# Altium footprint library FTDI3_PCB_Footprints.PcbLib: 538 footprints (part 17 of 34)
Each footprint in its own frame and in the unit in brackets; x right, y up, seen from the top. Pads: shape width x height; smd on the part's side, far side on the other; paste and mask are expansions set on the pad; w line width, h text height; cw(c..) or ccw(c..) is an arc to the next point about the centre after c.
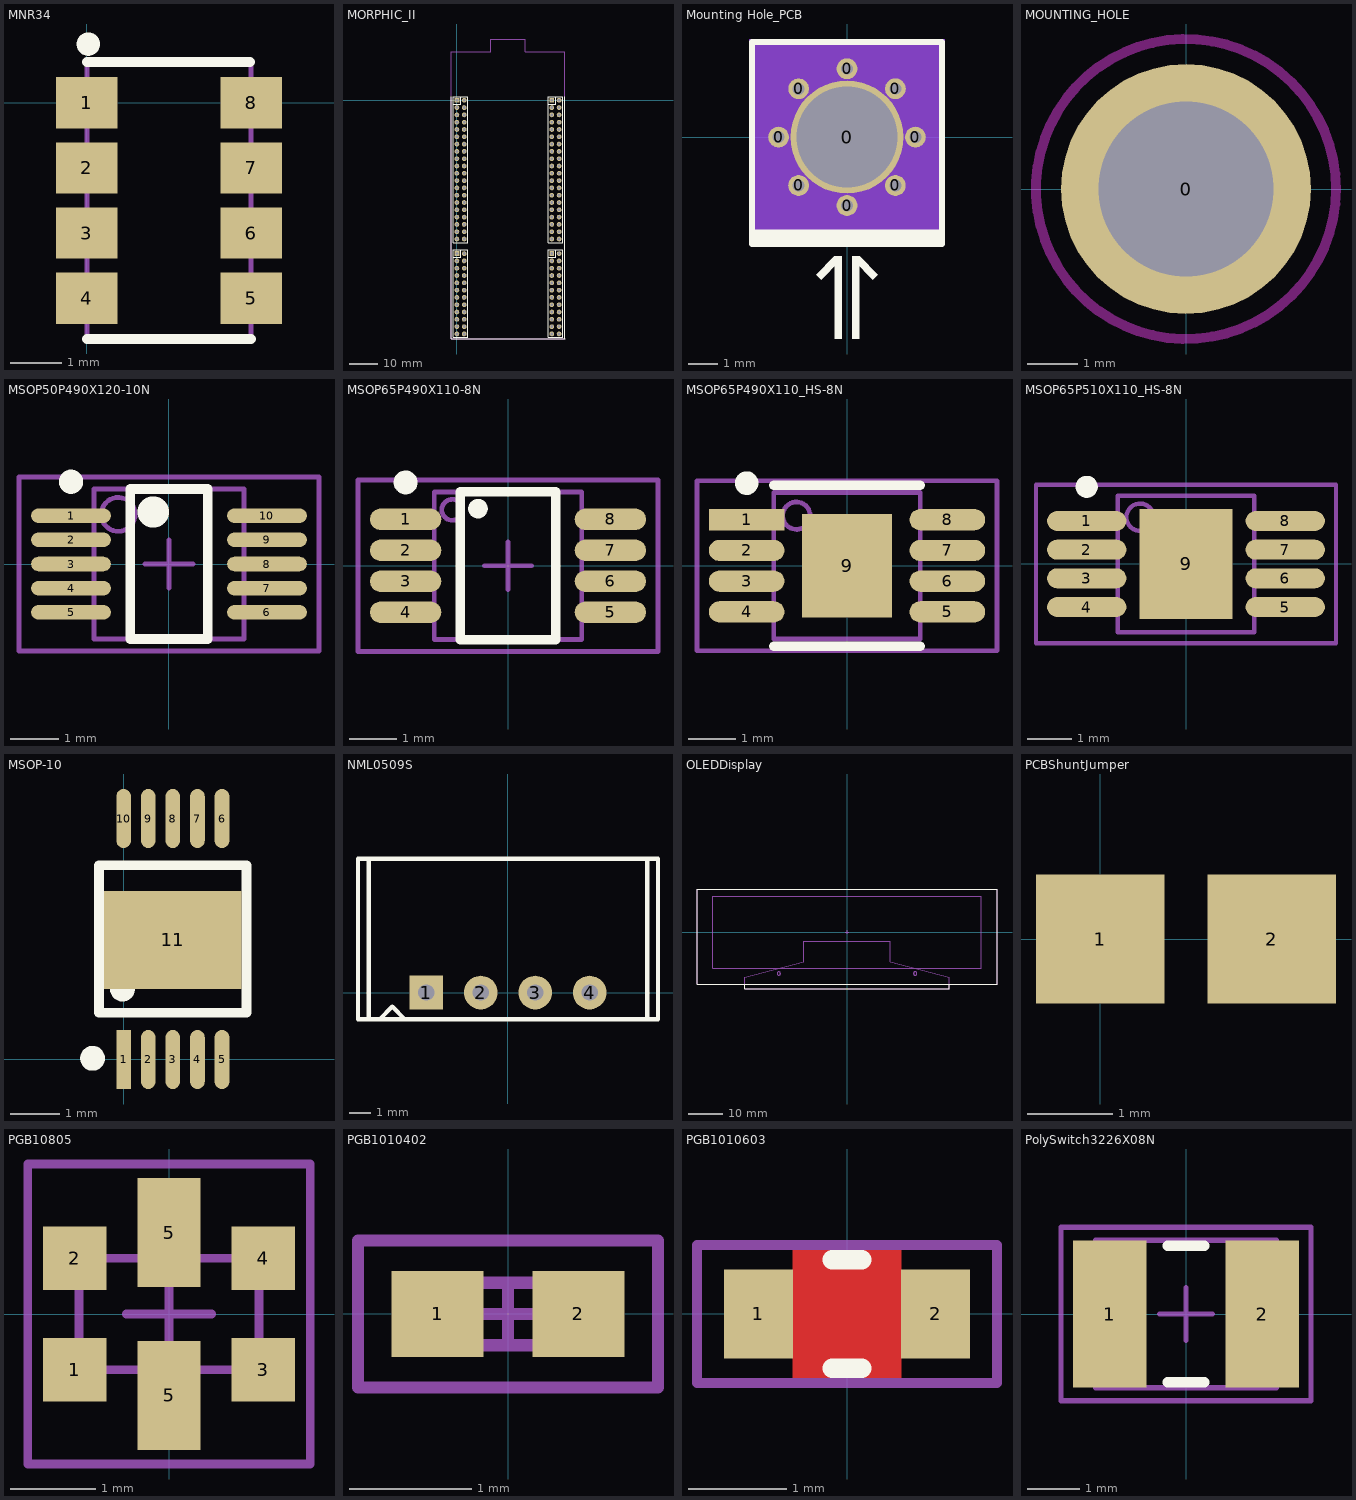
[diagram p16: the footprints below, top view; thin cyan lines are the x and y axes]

## MNR34 [mm] "3216x4 Resistor Array"
height 0.55
pads (8):
  rect 1.2x1 smd: 1(0,0) 2(0,-1.27) 3(0,-2.54) 4(0,-3.81) 5(3.2,-3.81) 6(3.2,-2.54) 7(3.2,-1.27) 8(3.2,0)
Top Overlay:
  circle w0.254: c0.027,1.143 r0.1
  lines w0.2: 0,-4.605 3.2,-4.605 ; 0,0.795 3.175,0.795
M13_Assembly_Info:
  lines w0.1: 0,-4.605 0,0.795 3.2,0.795 3.2,-4.605 0,-4.605
3D body: height 0, standoff 0, extent 0,-4.605 3.2,0.795

## MORPHIC_II [mil] "MorphIC II Module"
pads (128):
  rect 65x65 hole 39.37: 1(0,0) 41(1300,0) 81(0,-2100) 105(1300,-2100)
  round 65 hole 39.37: 2(100,0) 3(0,-100) 4(100,-100) 5(0,-200) 6(100,-200) 7(0,-300) 8(100,-300) 9(0,-400) 10(100,-400) 11(0,-500) 12(100,-500) 13(0,-600) 14(100,-600) 15(0,-700) 16(100,-700) 17(0,-800) 18(100,-800) 19(0,-900) 20(100,-900) 21(0,-1000) 22(100,-1000) 23(0,-1100) 24(100,-1100) 25(0,-1200) 26(100,-1200) 27(0,-1300) 28(100,-1300) 29(0,-1400) 30(100,-1400) 31(0,-1500) 32(100,-1500) 33(0,-1600) 34(100,-1600) 35(0,-1700) 36(100,-1700) 37(0,-1800) 38(100,-1800) 39(0,-1900) 40(100,-1900) 42(1400,0) 43(1300,-100) 44(1400,-100) 45(1300,-200) 46(1400,-200) 47(1300,-300) 48(1400,-300) 49(1300,-400) 50(1400,-400) 51(1300,-500) 52(1400,-500) 53(1300,-600) 54(1400,-600) 55(1300,-700) 56(1400,-700) 57(1300,-800) 58(1400,-800) 59(1300,-900) 60(1400,-900) 61(1300,-1000) 62(1400,-1000) 63(1300,-1100) 64(1400,-1100) 65(1300,-1200) 66(1400,-1200) 67(1300,-1300) 68(1400,-1300) 69(1300,-1400) 70(1400,-1400) 71(1300,-1500) 72(1400,-1500) 73(1300,-1600) 74(1400,-1600) 75(1300,-1700) 76(1400,-1700) 77(1300,-1800) 78(1400,-1800) 79(1300,-1900) 80(1400,-1900) 82(100,-2100) 83(0,-2200) 84(100,-2200) 85(0,-2300) 86(100,-2300) 87(0,-2400) 88(100,-2400) 89(0,-2500) 90(100,-2500) 91(0,-2600) 92(100,-2600) 93(0,-2700) 94(100,-2700) 95(0,-2800) 96(100,-2800) 97(0,-2900) 98(100,-2900) 99(0,-3000) 100(100,-3000) 101(0,-3100) 102(100,-3100) 103(0,-3200) 104(100,-3200) 106(1400,-2100) 107(1300,-2200) 108(1400,-2200) 109(1300,-2300) 110(1400,-2300) 111(1300,-2400) 112(1400,-2400) 113(1300,-2500) 114(1400,-2500) 115(1300,-2600) 116(1400,-2600) 117(1300,-2700) 118(1400,-2700) 119(1300,-2800) 120(1400,-2800) 121(1300,-2900) 122(1400,-2900) 123(1300,-3000) 124(1400,-3000) 125(1300,-3100) 126(1400,-3100) 127(1300,-3200) 128(1400,-3200)
Top Overlay:
  lines w7.87: -78.74,50 -78.74,-3268.5 1477.95,-3268.5 1478.74,-3269.29 1478.74,50 ; -50,-2151.18 51.18,-2151.18 51.18,-2050 ; -50,-51.18 51.18,-51.18 51.18,50 ; 1250,-2151.18 1351.18,-2151.18 1351.18,-2050 ; 1250,-51.18 1351.18,-51.18 1351.18,50 ; -50,-3243.31 150,-3243.31 150,-2050 -50,-2050 -50,-3243.31 ; -50,-1950 150,-1950 150,50 -50,50 -50,-1950 ; 1250,-3243.31 1250,-2050 1450,-2050 1450,-3243.31 1250,-3243.31 ; 1250,-1950 1250,50 1450,50 1450,-1950 1250,-1950
M13_Assembly_Info:
  lines w7.87: 1477.95,-3268.5 -78.74,-3268.5 -78.74,661.42 461.81,661.42 461.81,839.37 938.19,839.37 938.19,661.42 1478.74,661.42 1478.74,-3269.29
3D body: height 314.96, standoff 0, extent 1250,-3243.11 1449.8,-2050.2
3D body: height 314.96, standoff 0, extent -50.2,-3243.11 149.61,-2050.2
3D body: height 314.96, standoff 0, extent 1250,-1949.8 1449.8,50.2
3D body: height 314.96, standoff 0, extent -50.2,-1949.8 149.61,50.2

## Mounting Hole_PCB [mm]
pads (9):
  round 0.7 hole 0.4 unplated: 0(-2.3,0) 0(-1.626,-1.626) 0(-1.625,1.625) 0(0,-2.3) 0(0,2.3) 0(1.625,-1.625) 0(1.627,1.627) 0(2.3,0)
  round 3.8 hole 3.4 paste+0.038 mask+0.2: 0(0,0)
Top Layer keep-out:
  region: 3.3,3.3 -3.3,3.3 -3.3,-3.3 3.3,-3.3
Bottom Layer keep-out:
  region: 3.3,3.3 -3.3,3.3 -3.3,-3.3 3.3,-3.3
Top Overlay:
  rectangle: -3.2,-3.7 3.2,-3.2
  region: -0.167,-3.993 -0.421,-3.993 -0.421,-6.787 -0.167,-6.787
  region: -1.05,-4.622 -0.87,-4.802 -0.242,-4.173 -0.421,-3.993
  rectangle: 0.167,-6.787 0.421,-3.993
  region: 0.421,-3.993 0.242,-4.173 0.87,-4.802 1.05,-4.622
  lines w0.2: -3.2,-3.6 -3.2,-3.2 ; 3.2,-3.6 3.2,-3.2 ; -3.2,-3.2 -3.2,3.2 3.2,3.2 3.2,-3.2 ; -3.2,-3.2 3.2,-3.2
Bottom Overlay:
  rectangle: -3.2,-3.6 3.2,-3.2
  lines w0.2: -3.2,-3.2 -3.2,-3.6 3.2,-3.6 3.2,-3.2 ; -3.2,-3.2 3.2,-3.2 ; -3.2,-3.2 -3.2,3.2 3.2,3.2 3.2,-3.2
Top Solder:
  region: 3.2,3.2 -3.2,3.2 -3.2,-3.2 3.2,-3.2
Bottom Solder:
  region: 3,3 -3,3 -3,-3 3,-3
Keep-Out Layer:
  circle w1.2: c0,0 r2.5

## MOUNTING_HOLE [mm] "3.5mm Mouting hole"
pads (1):
  round 5 hole 3.5: 0(0,0)
Keep-Out Layer:
  circle w0.2: c0,0 r3

## MSOP50P490X120-10N [mm] "MSOP, 10-Leads, Body 3.1x3.1mm (max), Pitch 0.50mm, IPC Medium Density"
height 1.2
pads (10):
  oval 1.65x0.3 smd: 1(-2.025,1) 2(-2.025,0.5) 3(-2.025,0) 4(-2.025,-0.5) 5(-2.025,-1) 6(2.025,-1) 7(2.025,-0.5) 8(2.025,0) 9(2.025,0.5) 10(2.025,1)
Top Overlay:
  circle w0.25: c-2.025,1.7 r0.125
  circle w0.6: c-0.325,1.075 r0.025
  lines w0.2: -0.8,-1.55 -0.8,1.55 0.8,1.55 0.8,-1.55 -0.8,-1.55
M13_Assembly_Info:
  circle w0.1: c-1.05,1.025 r0.35
  lines w0.1: -1.55,-1.55 -1.55,1.55 1.55,1.55 1.55,-1.55 -1.55,-1.55
M15_Country_Yard:
  lines w0.1: -0.5,0 0.5,0 ; 0,-0.5 0,0.5 ; -3.1,-1.8 -3.1,1.8 3.1,1.8 3.1,-1.8 -3.1,-1.8
3D body: height 1.2, standoff 0.15, extent -1.55,-1.55 1.55,1.55

## MSOP65P490X110-8N [mm] "MSOP, 8-Leads, Body 3.1x3.1mm (max), Pitch 0.65mm, IPC Medium Density"
height 1.1
pads (8):
  oval 1.5x0.45 smd: 1(-2.15,0.975) 2(-2.15,0.325) 3(-2.15,-0.325) 4(-2.15,-0.975) 5(2.15,-0.975) 6(2.15,-0.325) 7(2.15,0.325) 8(2.15,0.975)
Top Overlay:
  circle w0.2: c-0.63,1.2 r0.105
  circle w0.25: c-2.15,1.75 r0.125
  lines w0.2: -1,-1.55 1,-1.55 1,1.55 -1,1.55 -1,-1.55
M13_Assembly_Info:
  circle w0.1: c-1.17,1.175 r0.22
  lines w0.1: -1.55,-1.55 1.55,-1.55 1.55,1.55 -1.55,1.55 -1.55,-1.55
M15_Country_Yard:
  lines w0.1: -0.5,0 0.5,0 ; 0,-0.5 0,0.5 ; -3.15,-1.8 3.15,-1.8 3.15,1.8 -3.15,1.8 -3.15,-1.8
3D body: height 1.1, standoff 0.15, extent -1.55,-1.55 1.55,1.55

## MSOP65P490X110_HS-8N [mm] "MSOP, 8-Leads, Body 3.1x3.1mm (max), Pitch 0.65mm, with heat sink, IPC Medium Density"
height 1.1
pads (9):
  rect 1.6x0.45 smd: 1(-2.125,0.975)
  oval 1.6x0.45 smd: 2(-2.125,0.325) 3(-2.125,-0.325) 4(-2.125,-0.975) 5(2.125,-0.975) 6(2.125,-0.325) 7(2.125,0.325) 8(2.125,0.975)
  rect 1.9x2.2 smd: 9(0,0)
Top Overlay:
  circle w0.25: c-2.125,1.75 r0.125
  lines w0.2: -1.55,-1.7 1.55,-1.7 ; -1.55,1.7 1.55,1.7
M13_Assembly_Info:
  circle w0.1: c-1.07,1.06 r0.29
  lines w0.1: -1.55,-1.55 1.55,-1.55 1.55,1.55 -1.55,1.55 -1.55,-1.55
M15_Country_Yard:
  lines w0.1: -0.5,0 0.5,0 ; 0,-0.5 0,0.5 ; -3.175,-1.8 3.175,-1.8 3.175,1.8 -3.175,1.8 -3.175,-1.8
3D body: height 1.1, standoff 0.15, extent -1.55,-1.55 1.55,1.55

## MSOP65P510X110_HS-8N [mm] "MSOP, 8-Leads, Body 3.1x3.1mm (max), Pitch 0.65mm, IPC Medium Density"
height 1.1
pads (9):
  oval 1.8x0.45 smd: 1(-2.25,0.975) 2(-2.25,0.325) 3(-2.25,-0.325) 4(-2.25,-0.975) 5(2.25,-0.975) 6(2.25,-0.325) 7(2.25,0.325) 8(2.25,0.975)
  rect 2.1x2.5 smd: 9(0,0)
Top Overlay:
  circle w0.25: c-2.25,1.75 r0.125
M13_Assembly_Info:
  circle w0.1: c-1.04,1.06 r0.31
  lines w0.1: -1.55,-1.55 -1.55,1.55 1.55,1.55 1.55,-1.55 -1.55,-1.55
M15_Country_Yard:
  lines w0.1: -0.5,0 0.5,0 ; 0,-0.5 0,0.5 ; -3.4,-1.8 -3.4,1.8 3.4,1.8 3.4,-1.8 -3.4,-1.8
3D body: height 1.1, standoff 0.2, extent -1.55,-1.55 1.55,1.55

## MSOP-10 [mm] "MSE-Type MSOP-10 with exposed die pad"
pads (11):
  rect 0.3x1.2 smd: 1(0,0)
  oval 0.3x1.2 smd: 2(0.5,0) 3(1,0) 4(1.5,0) 5(2,0) 6(2,4.9) 7(1.5,4.9) 8(1,4.9) 9(0.5,4.9) 10(0,4.9)
  rect 2.8x2 smd: 11(1,2.43)
Top Overlay:
  lines w0.2: -0.5,0.95 2.5,0.95 2.5,3.95 -0.5,3.95 -0.5,0.95
  lines w0.254: -0.508,0 cw(c-0.631,0.025) -0.506,0.025 ; 0.098,1.405 cw(c-0.025,1.43) 0.1,1.43

## NML0509S [mil] "5V/9V, Step Up, DC-DC Converter"
height 393.7
pads (4):
  rect 62x62 hole 30: 1(-150,0)
  round 62 hole 30: 2(-50,0) 3(50,0) 4(150,0)
Top Overlay:
  lines w7.87: -188.98,-49.21 -212.6,-25.59 -236.22,-49.21 ; -236.22,-49.21 -236.22,-49.21
  lines w8: -255.91,-49.21 -255.91,246.06 ; 255.91,-49.21 255.91,246.06 ; -275.59,-49.21 -275.59,246.06 275.59,246.06 275.59,-49.21 -275.59,-49.21

## OLEDDisplay [mm] "UG-5664ALBBT02; Folding Type; OEL Display Module; 256x64 pixels; Monochrome; TCP Package"
height 4
Top Overlay:
  lines w0.2: -30,-15.225 -30,-16.575 30,-16.575 30,-15.225 ; -44,-15.225 44,-15.225 44,12.575 -44,12.575 -44,-15.225
M15_Country_Yard:
  circle w0.2: c-20,-12.125 r0.5
  circle w0.2: c20,-12.125 r0.5
  lines w0.1: -0.55,0 0.55,0 ; 0,-0.5 0,0.5 ; -44,-15.225 -44,12.575 44,12.575 44,-15.225 -44,-15.225 ; -39.4,-10.6 -39.4,10.575 39.375,10.575 39.375,-10.6 -39.4,-10.6 ; -30,-16.575 30,-16.575 30,-15.225 30,-13.25 12.75,-8.625 12.75,-5.625 12.75,-2.625 -12.75,-2.625 -12.75,-5.625 -12.75,-8.625 -30,-13.25 -30,-15.225 -30,-16.575

## PCBShuntJumper [mm]
pads (2):
  rect 1.5x1.5 smd: 1(0,0) 2(2,0)

## PGB10805 [mm]
pads (6):
  rect 0.737x0.737 smd: 1(-1.1,-0.65) 2(-1.1,0.65) 3(1.1,-0.65) 4(1.1,0.65)
  rect 0.737x1.27 smd: 5(0,-0.95) 5(0,0.95)
M13_Assembly_Info:
  lines w0.1: -1.05,-0.65 1.05,-0.65 1.05,0.65 -1.05,0.65 -1.05,-0.65
M15_Country_Yard:
  lines w0.1: -0.5,0 0.5,0 ; 0,-0.5 0,0.5 ; -1.65,-1.75 -1.65,1.75 1.65,1.75 1.65,-1.75 -1.65,-1.75
3D body: height 0, standoff 0, extent -1.05,-0.65 1.05,0.65

## PGB1010402 [mm] "TVS, PGB1010402, Littelfuse, 2-Leads, Body 1.0x0.5mm, IPC Medium Density"
height 0.3
pads (2):
  rect 0.75x0.7 smd: 1(-0.575,0) 2(0.575,0)
M13_Assembly_Info:
  lines w0.1: -0.495,-0.255 0.495,-0.255 0.495,0.255 -0.495,0.255 -0.495,-0.255
M15_Country_Yard:
  lines w0.1: -0.255,0 0.255,0 ; 0,-0.255 0,0.255 ; -1.225,-0.6 1.225,-0.6 1.225,0.6 -1.225,0.6 -1.225,-0.6
3D body: height 0.3, standoff 0, extent -0.495,-0.255 0.495,0.255

## PGB1010603 [mm] "Chip Transil, Littelfuse, PGB1 series, 2-Leads, Body 1.6x0.8mm, IPC Medium Density"
height 0.356
pads (2):
  rect 0.7x0.9 smd: 1(-0.9,0) 2(0.9,0)
Top Layer:
  pour cut-out: -0.55,-0.65 -0.55,0.65 0.55,0.65 0.55,-0.65
Top Overlay:
  lines w0.2: -0.15,-0.55 0.15,-0.55 ; -0.15,0.55 0.15,0.55
M13_Assembly_Info:
  lines w0.1: -0.8,-0.395 -0.8,0.395 0.8,0.395 0.8,-0.395 -0.8,-0.395
M15_Country_Yard:
  lines w0.1: -0.395,0 0.395,0 ; 0,-0.395 0,0.395 ; -1.525,-0.7 -1.525,0.7 1.525,0.7 1.525,-0.7 -1.525,-0.7
3D body: height 0.36, standoff 0, extent -0.8,-0.395 0.8,0.395

## PolySwitch3226X08N [mm] "PTC Fuse, 2-Leads, Body 3.2x2.6mm, IPC Medium Density"
height 0.76
pads (2):
  rect 1.4x2.8 smd: 1(-1.45,0) 2(1.45,0)
Top Overlay:
  lines w0.2: -0.35,-1.3 0.35,-1.3 ; -0.35,1.3 0.35,1.3
M13_Assembly_Info:
  lines w0.1: -1.715,-1.4 1.715,-1.4 1.715,1.4 -1.715,1.4 -1.715,-1.4
M15_Country_Yard:
  lines w0.1: -0.5,0 0.5,0 ; 0,-0.5 0,0.5 ; -2.375,-1.65 2.375,-1.65 2.375,1.65 -2.375,1.65 -2.375,-1.65
3D body: height 0.76, standoff 0, extent -1.715,-1.4 1.715,1.4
